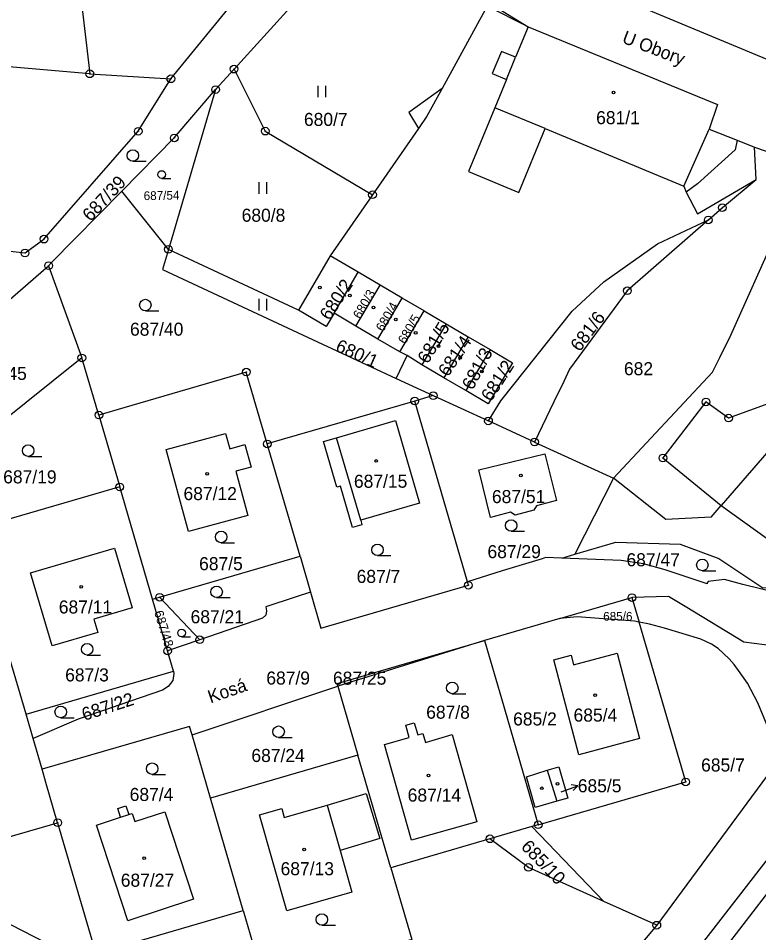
# Model space of a CAD drawing. Extents: x -749778 to -749372, y -967291 to -966955.
# Drawn here: x -749652.7 to -749556.3, y -967221.1 to -967101.9 of the extents above; entities that cross this region are included whole.
import ezdxf

# ---------------------------------------------------------------- set-up
doc = ezdxf.new("R2010")
doc.units = 0
for name, color, linetype in [('Hranice parcel', 7, 'Continuous'), ('Parcelní čísla', 7, 'Continuous'), ('Pop  PČ popisy', 7, 'Continuous'), ('Vnitřní kresba', 7, 'Continuous'), ('Značky bodu BP', 7, 'Continuous'), ('Značky budov', 7, 'Continuous'), ('Značky kultur', 7, 'Continuous')]:
    doc.layers.add(name, color=color, linetype=linetype)

msp = doc.modelspace()

# ---------------------------------------------------------------- linework, layer by layer
at = {"layer": 'Hranice parcel'}
for p, q in [((-749576.24, -967098.5), (-749554.23, -967107.67)), ((-749586.36, -967103.02), (-749591.67, -967100.33)), ((-749643.43, -967109.15), (-749666.45, -967107.14)), ((-749627.05, -967111.2), (-749624.65, -967108.54)), ((-749643.43, -967109.15), (-749632.88, -967109.8)), ((-749627.05, -967111.2), (-749633.19, -967132.02)), ((-749633.19, -967132.02), (-749639.25, -967124.44)), ((-749606.62, -967124.91), (-749612.12, -967132.87)), ((-749616.27, -967139.94), (-749633.19, -967132.02)), ((-749612.12, -967132.87), (-749616.27, -967139.94)), ((-749608.49, -967135), (-749612.12, -967132.87)), ((-749665.32, -967148.46), (-749648.79, -967134.15)), ((-749648.79, -967134.15), (-749644.47, -967146.16)), ((-749611.63, -967140.35), (-749608.49, -967135)), ((-749605.63, -967136.68), (-749608.49, -967135)), ((-749608.77, -967142.03), (-749605.63, -967136.68)), ((-749602.77, -967138.36), (-749605.63, -967136.68)), ((-749605.91, -967143.71), (-749602.77, -967138.36)), ((-749599.91, -967140.04), (-749602.77, -967138.36)), ((-749608.77, -967142.03), (-749611.63, -967140.35)), ((-749603.05, -967145.39), (-749599.91, -967140.04)), ((-749599.91, -967140.04), (-749597.04, -967141.72)), ((-749605.91, -967143.71), (-749608.77, -967142.03)), ((-749597.04, -967141.72), (-749600.18, -967147.07)), ((-749597.04, -967141.72), (-749594.18, -967143.4)), ((-749603.05, -967145.39), (-749605.91, -967143.71)), ((-749594.18, -967143.4), (-749597.32, -967148.75)), ((-749594.18, -967143.4), (-749591.31, -967145.08)), ((-749602.11, -967145.85), (-749603.05, -967145.39)), ((-749591.31, -967145.08), (-749594.45, -967150.43)), ((-749644.47, -967146.16), (-749661.16, -967159.51)), ((-749642.25, -967153.61), (-749644.47, -967146.16)), ((-749603.56, -967148.86), (-749602.11, -967145.85)), ((-749600.18, -967147.07), (-749602.11, -967145.85)), ((-749597.32, -967148.75), (-749600.18, -967147.07)), ((-749603.56, -967148.86), (-749598.71, -967151.08)), ((-749594.45, -967150.43), (-749597.32, -967148.75)), ((-749598.71, -967151.08), (-749601.12, -967151.78)), ((-749598.71, -967151.08), (-749591.52, -967154.37)), ((-749601.12, -967151.78), (-749620.32, -967157.37)), ((-749594.26, -967175.33), (-749601.12, -967151.78)), ((-749642.25, -967153.61), (-749639.53, -967162.97)), ((-749585.52, -967157.12), (-749591.52, -967154.37)), ((-749616.06, -967172.01), (-749620.32, -967157.37)), ((-749585.52, -967157.12), (-749575.24, -967161.82)), ((-749575.24, -967161.82), (-749580.28, -967171.75)), ((-749639.53, -967162.97), (-749658.73, -967168.56)), ((-749635.26, -967177.61), (-749639.53, -967162.97)), ((-749581.95, -967172.24), (-749580.28, -967171.75)), ((-749634.34, -967177.34), (-749616.06, -967172.01)), ((-749616.06, -967172.01), (-749614.7, -967176.68)), ((-749635.26, -967177.61), (-749634.34, -967177.34)), ((-749633.31, -967184.33), (-749635.26, -967177.61)), ((-749634.34, -967177.34), (-749629.11, -967182.88)), ((-749582.24, -967180.13), (-749572.83, -967177.39)), ((-749572.83, -967177.39), (-749571.89, -967180.6)), ((-749582.24, -967180.13), (-749592.03, -967182.99)), ((-749651.74, -967192.56), (-749654.61, -967182.72)), ((-749629.11, -967182.88), (-749633.31, -967184.33)), ((-749592.03, -967182.99), (-749611.14, -967188.93)), ((-749632.54, -967186.97), (-749633.31, -967184.33)), ((-749651.74, -967192.56), (-749632.54, -967186.97)), ((-749630.12, -967195.27), (-749611.14, -967188.93)), ((-749611.14, -967188.93), (-749608.51, -967197.94)), ((-749650.82, -967195.73), (-749651.74, -967192.56)), ((-749649.64, -967199.76), (-749650.82, -967195.73)), ((-749627.72, -967203.53), (-749630.12, -967195.27)), ((-749608.51, -967197.94), (-749627.72, -967203.53)), ((-749604.25, -967212.58), (-749608.51, -967197.94)), ((-749553.95, -967198.86), (-749569.6, -967220.07)), ((-749623.45, -967218.17), (-749627.72, -967203.53)), ((-749666.82, -967212.31), (-749647.62, -967206.72)), ((-749585.87, -967207.23), (-749591.33, -967208.82)), ((-749585.04, -967206.99), (-749585.87, -967207.23)), ((-749585.87, -967207.23), (-749576.49, -967216.97)), ((-749591.33, -967208.82), (-749604.25, -967212.58)), ((-749569.6, -967220.07), (-749576.49, -967216.97))]:
    msp.add_line(p, q, dxfattribs=at)
for points in [[(-749648.62, -967064.74), (-749648.3, -967067.53), (-749647.94, -967070.71), (-749643.43, -967109.15)], [(-749632.88, -967109.8), (-749617.06, -967090.42), (-749615.32, -967085.21)], [(-749615.32, -967085.21), (-749606.8, -967090.45), (-749586.36, -967103.02)], [(-749624.65, -967108.54), (-749609.2, -967091.46), (-749591.67, -967100.33)], [(-749591.67, -967100.33), (-749597.57, -967111.08), (-749601.91, -967114.2), (-749600.64, -967116.26), (-749606.62, -967124.91)], [(-749586.36, -967103.02), (-749561.68, -967113.13), (-749562.79, -967116.35), (-749559.15, -967117.81), (-749556.87, -967118.72)], [(-749624.65, -967108.54), (-749620.59, -967116.62), (-749606.62, -967124.91)], [(-749676.68, -967129.73), (-749651.87, -967132.49), (-749649.4, -967130.69), (-749637.12, -967116.63), (-749632.88, -967109.8)], [(-749639.25, -967124.44), (-749632.43, -967117.5), (-749627.05, -967111.2)], [(-749562.89, -967128.18), (-749561.06, -967126.58), (-749556.64, -967122.92), (-749556.87, -967118.72)], [(-749556.87, -967118.72), (-749552.69, -967120.13), (-749549.11, -967121.42)], [(-749648.79, -967134.15), (-749648.4, -967133.75), (-749639.25, -967124.44)], [(-749591.52, -967154.37), (-749589.9, -967151.74), (-749580.64, -967140.09), (-749576.51, -967136.23), (-749569.51, -967131.32), (-749562.89, -967128.18)], [(-749562.89, -967128.18), (-749573.44, -967137.41), (-749580.98, -967147.62), (-749581.71, -967149.24), (-749582.99, -967151.9), (-749585.52, -967157.12)], [(-749575.24, -967161.82), (-749562.35, -967148.01), (-749561.39, -967146.09), (-749559.94, -967143.18), (-749554, -967129.9)], [(-749554, -967129.9), (-749548.6, -967132), (-749545.4, -967138.1), (-749553.6, -967150.87), (-749554.2, -967151.8), (-749560.25, -967154), (-749563.2, -967151.9), (-749568.8, -967159.2), (-749561.22, -967165.4), (-749549.18, -967174.04), (-749542.77, -967166.07), (-749545.93, -967163), (-749545.74, -967162.82)], [(-749633.19, -967132.02), (-749633.97, -967134.65), (-749615.09, -967143.47), (-749603.56, -967148.86)], [(-749611.63, -967140.35), (-749612.64, -967142.07), (-749616.27, -967139.94)], [(-749591.31, -967145.08), (-749588.4, -967146.79), (-749591.54, -967152.14), (-749594.45, -967150.43)], [(-749620.32, -967157.37), (-749623.05, -967148.01), (-749638.99, -967152.66), (-749642.25, -967153.61)], [(-749603.61, -967154.33), (-749600.48, -967165.08), (-749608.16, -967167.31), (-749607.99, -967167.89), (-749609.24, -967168.25), (-749610.8, -967162.88), (-749611.28, -967163.02), (-749613.01, -967157.07), (-749611.29, -967156.56), (-749603.61, -967154.33)], [(-749633.47, -967158.1), (-749625.75, -967156.01), (-749625.21, -967157.99), (-749623.23, -967157.46), (-749622.44, -967160.41), (-749624.42, -967160.94), (-749622.87, -967166.68), (-749630.59, -967168.77), (-749633.47, -967158.1)], [(-749582.65, -967164.76), (-749585.26, -967165.42), (-749585.62, -967166.02), (-749588.05, -967166.64), (-749588.66, -967166.28), (-749591.26, -967166.94), (-749592.77, -967160.76), (-749584.2, -967158.65), (-749582.65, -967164.76)], [(-749580.28, -967171.75), (-749574.93, -967170.19), (-749566.54, -967170.41), (-749561.52, -967172.29), (-749555.8, -967176.14), (-749551.55, -967175.94), (-749534.4, -967172.34)], [(-749648.35, -967183.67), (-749651.14, -967174.17), (-749640.2, -967170.95), (-749637.92, -967178.72), (-749642.91, -967180.19), (-749642.4, -967181.92), (-749648.35, -967183.67)], [(-749581.95, -967172.24), (-749584.09, -967172.15), (-749584.51, -967172.35), (-749589.74, -967173.9), (-749594.26, -967175.33)], [(-749537.02, -967175.91), (-749538.03, -967174.36), (-749538.28, -967173.97), (-749538.76, -967173.43), (-749541.48, -967175.55), (-749543.56, -967176.77), (-749545.65, -967177.56), (-749547.19, -967177.95), (-749547.26, -967177.59), (-749549.92, -967177.81), (-749550.89, -967177.68), (-749553.79, -967176.8), (-749558.39, -967175.68), (-749560.79, -967175.03), (-749562.93, -967175.31), (-749563.04, -967175.46), (-749563.04, -967175.6), (-749568.49, -967173.77), (-749571.33, -967173.01), (-749574.23, -967172.55), (-749581.95, -967172.24)], [(-749614.7, -967176.68), (-749613.33, -967181.38), (-749594.13, -967175.78), (-749594.26, -967175.33)], [(-749614.7, -967176.68), (-749616.71, -967177.34), (-749620.52, -967178.6), (-749620.41, -967179.11), (-749620.53, -967179.68), (-749620.96, -967180.05), (-749629.11, -967182.88)], [(-749540.92, -967181.19), (-749552.88, -967183.89), (-749558.28, -967183.21), (-749565.92, -967178.54), (-749568.07, -967177.26), (-749572.83, -967177.39)], [(-749571.89, -967180.6), (-749572.51, -967180.48), (-749579.99, -967179.88), (-749582.24, -967180.13)], [(-749585.04, -967206.99), (-749565.84, -967201.4), (-749571.89, -967180.6)], [(-749553.95, -967198.86), (-749554.04, -967198.48), (-749554.32, -967197.29), (-749554.75, -967195.73), (-749555.32, -967193.83), (-749556.46, -967191.11), (-749557.79, -967188.52), (-749558.73, -967187.21), (-749559.52, -967186.11), (-749560.17, -967185.38), (-749561.59, -967184.04), (-749562.48, -967183.46), (-749563.86, -967182.82), (-749568.6, -967181.36), (-749570.54, -967180.87), (-749571.89, -967180.6)], [(-749611.14, -967188.93), (-749611.24, -967188.58), (-749592.03, -967182.99)], [(-749592.03, -967182.99), (-749589.83, -967190.55), (-749585.04, -967206.99)], [(-749580.43, -967186.14), (-749574.77, -967184.65), (-749571.84, -967195.77), (-749579.77, -967197.86), (-749583.03, -967185.48), (-749580.76, -967184.88), (-749580.43, -967186.14)], [(-749632.54, -967186.97), (-749632.49, -967187.26), (-749632.64, -967188.19), (-749633.23, -967188.96), (-749633.98, -967189.45), (-749644.94, -967193.24), (-749650.82, -967195.73)], [(-749630.12, -967195.27), (-749630.44, -967194.17), (-749649.64, -967199.76)], [(-749596.23, -967195.22), (-749593.02, -967206.61), (-749601.53, -967209.01), (-749605.06, -967196.51), (-749601.83, -967195.6), (-749602.28, -967194.01), (-749601.18, -967193.7), (-749600.73, -967195.29), (-749600.06, -967195.1), (-749599.73, -967196.25), (-749596.23, -967195.22)], [(-749576.96, -967239.3), (-749574.4, -967236.29), (-749544.44, -967197.63)], [(-749647.62, -967206.72), (-749649.14, -967201.48), (-749649.64, -967199.76)], [(-749582.34, -967199.46), (-749581.19, -967203.52), (-749582.61, -967203.92), (-749585.43, -967204.73), (-749586.56, -967200.74), (-749583.87, -967199.89), (-749582.34, -967199.46)], [(-749617.77, -967218.2), (-749621.33, -967205.69), (-749618.44, -967204.87), (-749618.11, -967206.02), (-749612.53, -967204.43), (-749607.44, -967202.9), (-749605.67, -967208.79), (-749610.85, -967210.34), (-749609.3, -967215.79), (-749617.77, -967218.2)], [(-749637.91, -967205.5), (-749637.56, -967206.57), (-749633.66, -967205.29), (-749629.92, -967216.68), (-749638.47, -967219.49), (-749642.55, -967207.04), (-749639.42, -967206.01), (-749639.79, -967204.87), (-749638.74, -967204.53), (-749638.37, -967205.67), (-749637.91, -967205.5)], [(-749647.62, -967206.72), (-749642.66, -967223.76), (-749623.45, -967218.17)], [(-749576.49, -967216.97), (-749586.31, -967212.55), (-749591.33, -967208.82)], [(-749604.25, -967212.58), (-749601.52, -967221.94), (-749609.19, -967224.17), (-749616.05, -967236.54)], [(-749662.69, -967215.35), (-749653.68, -967220.04), (-749641.76, -967226.16), (-749629.68, -967230.35), (-749627.23, -967231.85), (-749624.5, -967234)], [(-749623.45, -967218.17), (-749620.73, -967227.53), (-749618.3, -967235.87)], [(-749569.6, -967220.07), (-749572.84, -967223.93), (-749575.56, -967227.17), (-749591.58, -967246.27)]]:
    msp.add_lwpolyline(points, dxfattribs=at)
at = {"layer": 'Pop  PČ popisy'}
for p, q in [((-749582.06, -967202.69), (-749579.89, -967201.9)), ((-749579.89, -967201.9), (-749580.74, -967201.8)), ((-749579.89, -967201.9), (-749580.48, -967202.53))]:
    msp.add_line(p, q, dxfattribs=at)
at = {"layer": 'Vnitřní kresba'}
for p, q in [((-749586.36, -967103.02), (-749587.99, -967107)), ((-749589.84, -967106.24), (-749591.02, -967109.11)), ((-749587.99, -967107), (-749589.84, -967106.24)), ((-749589.16, -967109.87), (-749587.99, -967107)), ((-749591.02, -967109.11), (-749589.16, -967109.87)), ((-749589.16, -967109.87), (-749590.68, -967113.57)), ((-749597.57, -967111.08), (-749599.55, -967114.67)), ((-749590.68, -967113.57), (-749594.13, -967121.88)), ((-749584.12, -967116.29), (-749590.68, -967113.57)), ((-749599.55, -967114.67), (-749600.64, -967116.26)), ((-749587.57, -967124.6), (-749584.12, -967116.29)), ((-749584.12, -967116.29), (-749566.06, -967123.79)), ((-749566.06, -967123.79), (-749562.79, -967116.35)), ((-749559.15, -967117.81), (-749559.39, -967119.06)), ((-749559.39, -967119.06), (-749564.28, -967123.48)), ((-749594.13, -967121.88), (-749587.57, -967124.6)), ((-749564.3, -967127.41), (-749556.64, -967122.92)), ((-749566.06, -967123.79), (-749565.77, -967124.57)), ((-749564.28, -967123.48), (-749565.77, -967124.57)), ((-749565.77, -967124.57), (-749564.3, -967127.41)), ((-749550.63, -967153.13), (-749561.22, -967165.4)), ((-749608.16, -967167.31), (-749611.29, -967156.56)), ((-749568.41, -967167.22), (-749575.24, -967161.82)), ((-749562.54, -967166.93), (-749561.22, -967165.4)), ((-749562.54, -967166.93), (-749568.41, -967167.22)), ((-749583.87, -967199.89), (-749582.61, -967203.92)), ((-749612.53, -967204.43), (-749610.85, -967210.34)), ((-749639.42, -967206.01), (-749638.37, -967205.67)), ((-749554.64, -967215.12), (-749572.33, -967238.1))]:
    msp.add_line(p, q, dxfattribs=at)
at = {"layer": 'Značky bodu BP'}
for centre, radius in [((-749643.43, -967109.15), 0.5), ((-749624.65, -967108.54), 0.5), ((-749624.65, -967108.54), 0.0303), ((-749643.43, -967109.15), 0.0303), ((-749632.88, -967109.8), 0.5), ((-749632.88, -967109.8), 0.0303), ((-749627.05, -967111.2), 0.5), ((-749627.05, -967111.2), 0.0303), ((-749637.12, -967116.63), 0.5), ((-749637.12, -967116.63), 0.0303), ((-749632.43, -967117.5), 0.5), ((-749620.59, -967116.62), 0.5), ((-749620.59, -967116.62), 0.0303), ((-749632.43, -967117.5), 0.0303), ((-749606.62, -967124.91), 0.5), ((-749606.62, -967124.91), 0.0303), ((-749561.06, -967126.58), 0.5), ((-749561.06, -967126.58), 0.0303), ((-749562.89, -967128.18), 0.5), ((-749562.89, -967128.18), 0.0303), ((-749649.4, -967130.69), 0.5), ((-749649.4, -967130.69), 0.0303), ((-749651.87, -967132.49), 0.5), ((-749651.87, -967132.49), 0.0303), ((-749633.19, -967132.02), 0.5), ((-749633.19, -967132.02), 0.0303), ((-749648.79, -967134.15), 0.5), ((-749648.79, -967134.15), 0.0303), ((-749573.44, -967137.41), 0.5), ((-749573.44, -967137.41), 0.0303), ((-749644.47, -967146.16), 0.5), ((-749644.47, -967146.16), 0.0303), ((-749623.05, -967148.01), 0.5), ((-749623.05, -967148.01), 0.0303), ((-749601.12, -967151.78), 0.5), ((-749598.71, -967151.08), 0.5), ((-749598.71, -967151.08), 0.0303), ((-749563.2, -967151.9), 0.5), ((-749601.12, -967151.78), 0.0303), ((-749563.2, -967151.9), 0.0303), ((-749642.25, -967153.61), 0.5), ((-749642.25, -967153.61), 0.0303), ((-749591.52, -967154.37), 0.5), ((-749560.25, -967154), 0.5), ((-749560.25, -967154), 0.0303), ((-749591.52, -967154.37), 0.0303), ((-749620.32, -967157.37), 0.5), ((-749620.32, -967157.37), 0.0303), ((-749585.52, -967157.12), 0.5), ((-749585.52, -967157.12), 0.0303), ((-749568.8, -967159.2), 0.5), ((-749568.8, -967159.2), 0.0303), ((-749639.53, -967162.97), 0.5), ((-749639.53, -967162.97), 0.0303), ((-749594.13, -967175.78), 0.5), ((-749594.13, -967175.78), 0.0303), ((-749634.34, -967177.34), 0.5), ((-749634.34, -967177.34), 0.0303), ((-749572.83, -967177.39), 0.5), ((-749572.83, -967177.39), 0.0303), ((-749629.11, -967182.88), 0.5), ((-749633.31, -967184.33), 0.5), ((-749629.11, -967182.88), 0.0303), ((-749633.31, -967184.33), 0.0303), ((-749565.84, -967201.4), 0.5), ((-749565.84, -967201.4), 0.0303), ((-749647.62, -967206.72), 0.5), ((-749585.04, -967206.99), 0.5), ((-749647.62, -967206.72), 0.0303), ((-749585.04, -967206.99), 0.0303), ((-749591.33, -967208.82), 0.5), ((-749591.33, -967208.82), 0.0303), ((-749586.31, -967212.55), 0.5), ((-749586.31, -967212.55), 0.0303), ((-749569.6, -967220.07), 0.5), ((-749569.6, -967220.07), 0.0303)]:
    msp.add_circle(centre, radius, dxfattribs=at)
at = {"layer": 'Značky budov'}
for centre in [(-749575.22, -967111.58), (-749613.49, -967136.98), (-749609.57, -967138.02), (-749606.5, -967139.59), (-749603.6, -967141.17), (-749601, -967142.9), (-749598.04, -967144.64), (-749595.21, -967146.15), (-749592.38, -967147.94), (-749606.15, -967159.59), (-749628.15, -967161.26), (-749587.31, -967161.48), (-749644.54, -967176), (-749577.64, -967190.09), (-749599.32, -967200.57), (-749582.54, -967201.65), (-749584.56, -967202.24), (-749615.53, -967210.2), (-749636.35, -967211.33)]:
    msp.add_circle(centre, 0.175, dxfattribs=at)
at = {"layer": 'Značky kultur'}
for p, q in [((-749613.69, -967112.2), (-749613.69, -967110.7)), ((-749612.69, -967112.2), (-749612.69, -967110.7)), ((-749637.83, -967120.55), (-749636.08, -967120.55)), ((-749634.06, -967122.77), (-749632.88, -967122.77)), ((-749621.4, -967124.77), (-749621.4, -967123.27)), ((-749620.4, -967124.77), (-749620.4, -967123.27)), ((-749621.38, -967139.97), (-749621.38, -967138.47)), ((-749620.38, -967139.97), (-749620.38, -967138.47)), ((-749636.2, -967140.03), (-749634.45, -967140.03)), ((-749651.45, -967158.99), (-749649.7, -967158.99)), ((-749588.56, -967168.75), (-749586.81, -967168.75)), ((-749626.33, -967170.24), (-749624.58, -967170.24)), ((-749605.97, -967171.92), (-749604.22, -967171.92)), ((-749563.67, -967173.89), (-749561.92, -967173.89)), ((-749626.92, -967177.4), (-749625.17, -967177.4)), ((-749631.47, -967182.5), (-749630.3, -967182.5)), ((-749643.77, -967184.87), (-749642.02, -967184.87)), ((-749596.23, -967189.91), (-749594.48, -967189.91)), ((-749647.22, -967193.04), (-749645.47, -967193.04)), ((-749618.85, -967195.62), (-749617.1, -967195.62)), ((-749635.32, -967200.43), (-749633.57, -967200.43)), ((-749613.21, -967220.09), (-749611.46, -967220.09))]:
    msp.add_line(p, q, dxfattribs=at)
for centre, radius in [((-749637.83, -967119.8), 0.75), ((-749634.06, -967122.27), 0.502), ((-749636.2, -967139.28), 0.75), ((-749651.45, -967158.24), 0.75), ((-749588.56, -967168), 0.75), ((-749626.33, -967169.49), 0.75), ((-749605.97, -967171.17), 0.75), ((-749563.67, -967173.14), 0.75), ((-749626.92, -967176.65), 0.75), ((-749631.48, -967182), 0.502), ((-749643.77, -967184.12), 0.75), ((-749596.23, -967189.16), 0.75), ((-749647.22, -967192.29), 0.75), ((-749618.85, -967194.87), 0.75), ((-749635.32, -967199.68), 0.75), ((-749613.21, -967219.34), 0.75)]:
    msp.add_circle(centre, radius, dxfattribs=at)

# ---------------------------------------------------------------- texts
at = {"layer": 'Parcelní čísla'}
for s, height, p in [('680/7', 1.7, (-749615.55, -967115.94)), ('681/1', 1.7, (-749577.5, -967115.71)), ('680/8', 1.7, (-749623.66, -967128.42)), ('687/40', 1.7, (-749638.2, -967143.27)), ('682', 1.7, (-749573.88, -967148.42)), ('687/45', 1.7, (-749658.59, -967149.03)), ('687/19', 1.7, (-749654.71, -967162.51)), ('687/15', 1.7, (-749609.04, -967163.08)), ('687/12', 1.7, (-749631.23, -967164.69)), ('687/51', 1.7, (-749591.07, -967165.08)), ('687/29', 1.7, (-749591.65, -967172.25)), ('687/47', 1.7, (-749573.55, -967173.31)), ('687/5', 1.7, (-749629.2, -967173.82)), ('687/7', 1.7, (-749608.69, -967175.48)), ('687/11', 1.7, (-749647.47, -967179.46)), ('687/21', 1.7, (-749630.31, -967180.74)), ('685/6', 1.139, (-749576.58, -967180.4)), ('687/3', 1.7, (-749646.64, -967188.31)), ('687/9', 1.7, (-749620.45, -967188.72)), ('687/25', 1.7, (-749611.77, -967188.74)), ('687/8', 1.7, (-749599.63, -967193.17)), ('685/4', 1.7, (-749580.44, -967193.55)), ('685/2', 1.7, (-749588.31, -967194.05)), ('687/24', 1.7, (-749622.39, -967198.81)), ('685/7', 1.7, (-749563.83, -967200.05)), ('685/5', 1.7, (-749579.89, -967202.76)), ('687/4', 1.7, (-749638.24, -967203.89)), ('687/14', 1.7, (-749602.04, -967203.97)), ('687/13', 1.7, (-749618.59, -967213.56)), ('687/27', 1.7, (-749639.4, -967215.06))]:
    msp.add_text(s, height=height, dxfattribs=at).set_placement(p)
for s, height, rotation, p in [('687/39', 1.7, 47, (-749643.33, -967128.49)), ('687/54', 1.139, 1, (-749636.41, -967125.61)), ('680/2', 1.7, 57, (-749612.2, -967141.39)), ('680/3', 1.2, 60, (-749608.2, -967141.18)), ('680/4', 1.2, 60, (-749605.23, -967142.83)), ('680/5', 1.2, 60, (-749602.35, -967144.45)), ('681/6', 1.7, 53, (-749579.64, -967145.46)), ('681/5', 1.7, 59, (-749599.42, -967147.04)), ('681/4', 1.7, 56, (-749596.8, -967148.73)), ('680/1', 1.7, 336, (-749611.56, -967145.21)), ('681/3', 1.7, 62, (-749593.58, -967150.45)), ('681/2', 1.7, 57, (-749591.19, -967151.96)), ('687/48', 1.2, 287, (-749635.07, -967179.28)), ('687/22', 1.7, 18, (-749644.15, -967193.47)), ('685/10', 1.7, 314, (-749587.39, -967209.95))]:
    msp.add_text(s, height=height, rotation=rotation, dxfattribs=at).set_placement(p)
at = {"layer": 'Pop  PČ popisy'}
for s, rotation, p in [('U Obory', 339, (-749574.24, -967105.06)), ('Kosá', 19, (-749627.72, -967191.18))]:
    msp.add_text(s, height=1.7, rotation=rotation, dxfattribs=at).set_placement(p)

doc.saveas('drawing.dxf')
